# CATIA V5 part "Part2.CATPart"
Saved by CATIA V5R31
Part number: Part2
Bounding box of the stored display mesh (mm): x -29.913 to 29.913, y -29.913 to 29.913, z -89.119 to 0
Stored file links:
  D:\PROJECTS\Project 2021\US EDITION\CATIA V5 6R 2021\Resources\Part Files\c12_catia_v5_6r2021_prt\c12_catia_v5-6r2021 figr_12-35\Part2.CATPart
  C:\CATIA-V5R13-manuscript\catia-v5r13-solid-models-090204\c11\Figure 11-35\Figure 11-35.CATProduct
  D:\PROJECTS\Project 2021\US EDITION\CATIA V5 6R 2021\Resources\Part Files\c12_catia_v5_6r2021_prt\c12_catia_v5-6r2021 figr_12-35\Base.CATPart
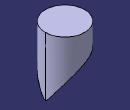
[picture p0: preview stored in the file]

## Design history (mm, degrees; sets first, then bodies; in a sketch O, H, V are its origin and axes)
Set1
  DatumSurface1: linked copy from another document
Body1 (main body)
  Sketch1 on xy-plane, origin (0, 0, 0), H (1, 0, 0), V (0, 1, 0)
    circle A1 centre (0, 0) radius 29.9132
  Pad1: profile Sketch1, direction (0, 0, 1), up to face of DatumSurface1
